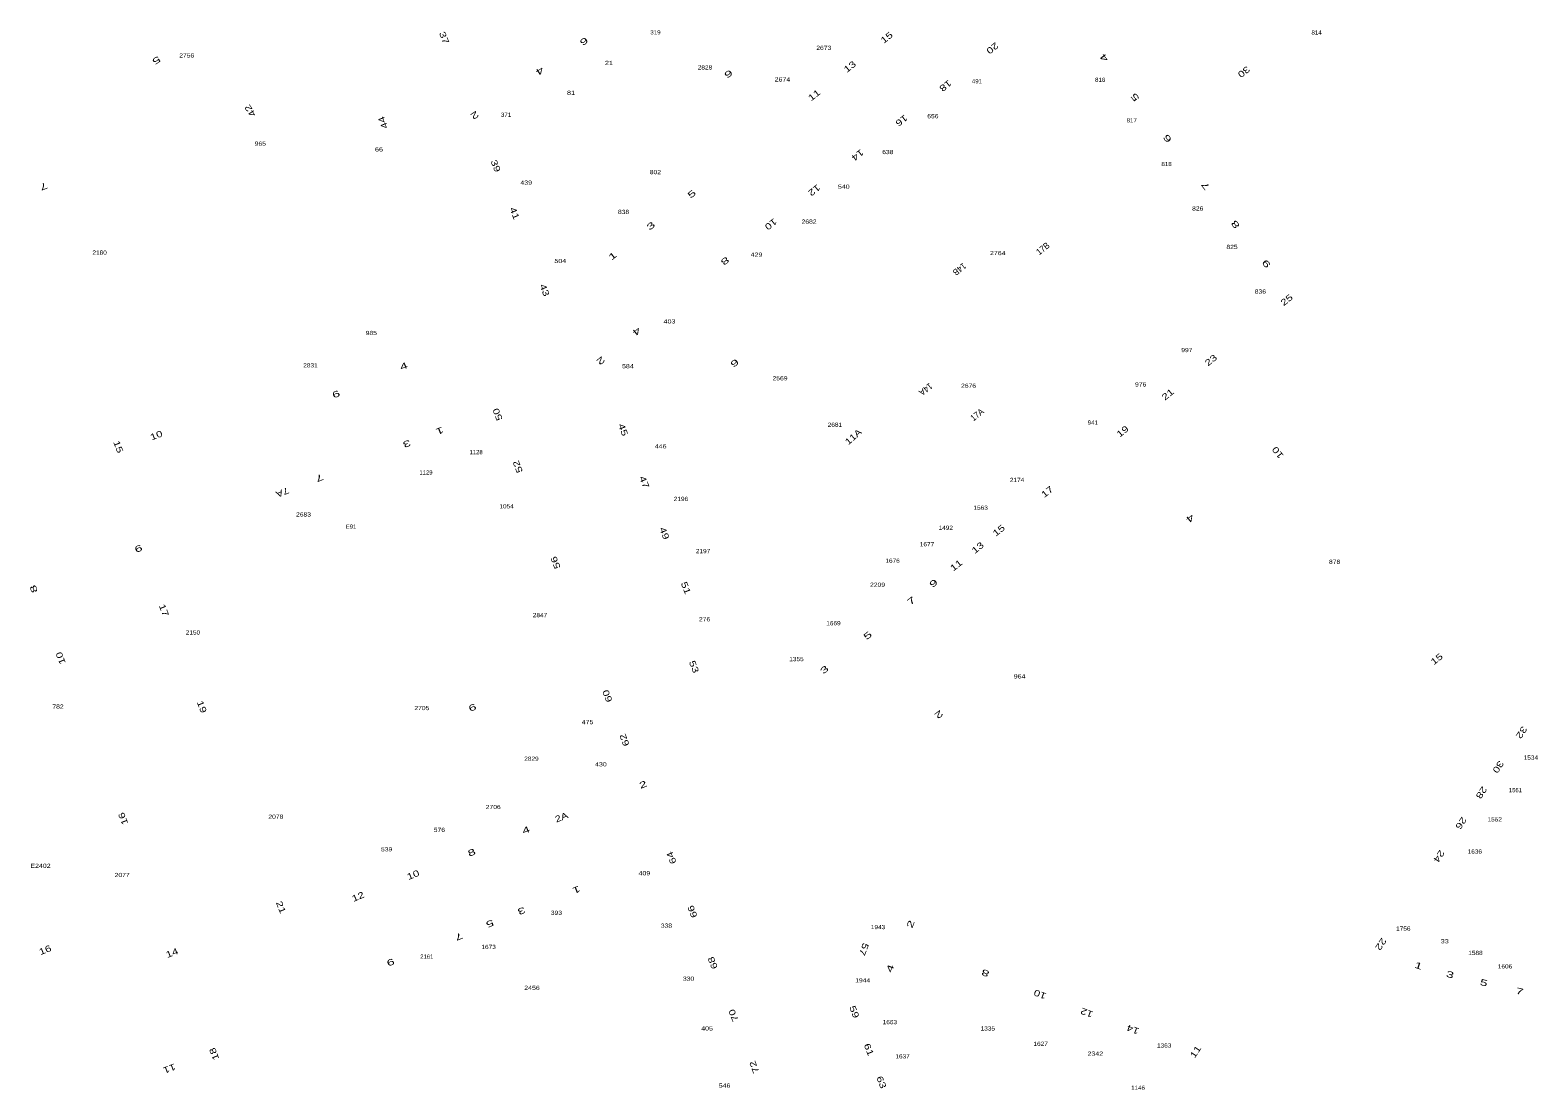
# Model space of a CAD drawing. Extents: x -828673 to -815583, y -1077737 to -1063807.
# Drawn here: x -821832.5 to -821473.2, y -1071355.2 to -1071102.6 of the extents above; entities that cross this region are included whole.
import ezdxf
from ezdxf.enums import TextEntityAlignment as Align

# ---------------------------------------------------------------- set-up
doc = ezdxf.new("R2010")
doc.units = 0
doc.header["$LTSCALE"] = 0.4
doc.layers.add('1', color=7, linetype='Continuous')
doc.layers.add('2', color=7, linetype='Continuous')

msp = doc.modelspace()

# ---------------------------------------------------------------- texts
at = {"layer": '1'}
for s, width, p in [('319', 1.1, (-821683.492, -1071103.658)), ('814', 1.1, (-821525.922, -1071103.687)), ('2756', 1.2, (-821795.197, -1071109.174)), ('2673', 1.2, (-821643.373, -1071107.358)), ('21', 1.3, (-821694.564, -1071110.951)), ('2828', 1.15, (-821671.69, -1071112.02)), ('2674', 1.25, (-821653.223, -1071114.887)), ('491', 1.1, (-821606.867, -1071115.322)), ('816', 1.1, (-821577.505, -1071114.974)), ('81', 1.3, (-821703.609, -1071118.064)), ('371', 1.1, (-821719.091, -1071123.306)), ('656', 1.2, (-821617.377, -1071123.645)), ('817', 1.1, (-821569.991, -1071124.639)), ('965', 1.2, (-821777.653, -1071130.189)), ('66', 1.3, (-821749.376, -1071131.56)), ('638', 1.2, (-821628.112, -1071132.192)), ('818', 1.1, (-821561.685, -1071135.038)), ('802', 1.2, (-821683.498, -1071136.969)), ('439', 1.25, (-821714.292, -1071139.475)), ('540', 1.25, (-821638.604, -1071140.443)), ('826', 1.2, (-821554.26, -1071145.644)), ('838', 1.2, (-821691.086, -1071146.452)), ('2682', 1.2, (-821646.878, -1071148.766)), ('2180', 1.15, (-821815.95, -1071156.15)), ('429', 1.25, (-821659.402, -1071156.641)), ('2764', 1.25, (-821601.897, -1071156.264)), ('825', 1.2, (-821546.073, -1071154.801)), ('504', 1.25, (-821706.175, -1071158.159)), ('836', 1.2, (-821539.325, -1071165.435)), ('403', 1.25, (-821680.138, -1071172.544)), ('985', 1.2, (-821751.206, -1071175.305)), ('997', 1.2, (-821556.847, -1071179.38)), ('2831', 1.15, (-821765.71, -1071183.01)), ('584', 1.25, (-821690.062, -1071183.229)), ('2569', 1.2, (-821653.795, -1071186.103)), ('2676', 1.2, (-821608.874, -1071187.873)), ('976', 1.2, (-821567.849, -1071187.569)), ('2681', 1.15, (-821640.718, -1071197.181)), ('941', 1.1, (-821579.254, -1071196.652)), ('446', 1.25, (-821682.24, -1071202.313)), ('1128', 1.05, (-821726.23, -1071203.704)), ('1129', 1.05, (-821738.179, -1071208.564)), ('2174', 1.15, (-821597.305, -1071210.322)), ('1054', 1.15, (-821718.971, -1071216.609)), ('2196', 1.15, (-821677.41, -1071214.842)), ('1563', 1.15, (-821605.982, -1071216.944)), ('2683', 1.2, (-821767.366, -1071218.549)), ('E91', 1.05, (-821756.031, -1071221.454)), ('1492', 1.15, (-821614.301, -1071221.732)), ('2197', 1.15, (-821672.139, -1071227.291)), ('1677', 1.15, (-821618.767, -1071225.659)), ('1676', 1.15, (-821626.98, -1071229.577)), ('878', 1.2, (-821521.63, -1071229.84)), ('2209', 1.2, (-821630.558, -1071235.305)), ('2847', 1.15, (-821711, -1071242.54)), ('276', 1.2, (-821671.781, -1071243.535)), ('1669', 1.15, (-821641.068, -1071244.478)), ('2150', 1.15, (-821793.703, -1071246.679)), ('1355', 1.15, (-821649.879, -1071253.025)), ('964', 1.25, (-821596.717, -1071257.148)), ('782', 1.2, (-821825.869, -1071264.342)), ('2705', 1.2, (-821739.157, -1071264.694)), ('475', 1.25, (-821699.67, -1071268.035)), ('2829', 1.15, (-821713.04, -1071276.76)), ('430', 1.25, (-821696.487, -1071278.09)), ('1534', 1.15, (-821474.866, -1071276.485)), ('1561', 1.05, (-821478.551, -1071284.259)), ('2706', 1.2, (-821722.147, -1071288.274)), ('2078', 1.2, (-821773.961, -1071290.585)), ('1552', 1.15, (-821483.474, -1071291.217)), ('576', 1.2, (-821734.986, -1071293.713)), ('539', 1.2, (-821747.55, -1071298.35)), ('1636', 1.15, (-821488.22, -1071298.886)), ('E2402', 1.25, (-821830.044, -1071302.294)), ('2077', 1.2, (-821810.58, -1071304.471)), ('409', 1.25, (-821686.111, -1071304.049)), ('393', 1.2, (-821707.091, -1071313.489)), ('338', 1.2, (-821680.873, -1071316.538)), ('1943', 1.15, (-821630.437, -1071316.887)), ('1756', 1.15, (-821505.258, -1071317.234)), ('1673', 1.15, (-821723.245, -1071321.619)), ('33', 1.3, (-821495.396, -1071320.265)), ('2161', 1.05, (-821737.98, -1071323.921)), ('1588', 1.15, (-821488.064, -1071323.041)), ('1606', 1.15, (-821481.019, -1071326.254)), ('2456', 1.25, (-821712.916, -1071331.366)), ('330', 1.2, (-821675.594, -1071329.186)), ('1944', 1.2, (-821634.09, -1071329.582)), ('1663', 1.15, (-821627.631, -1071339.54)), ('405', 1.25, (-821671.188, -1071341.038)), ('1335', 1.15, (-821604.281, -1071341.054)), ('1627', 1.15, (-821591.685, -1071344.708)), ('2342', 1.25, (-821578.668, -1071347.05)), ('1363', 1.15, (-821562.25, -1071345.113)), ('1637', 1.15, (-821624.588, -1071347.691)), ('546', 1.25, (-821667.027, -1071354.653)), ('1146', 1.1, (-821568.474, -1071355.165))]:
    msp.add_text(s, height=1, dxfattribs=dict(at, width=width)).set_placement(p, align=Align.CENTER)
at = {"layer": '2'}
for s, rotation, width, p in [('37', 291.749, 1.35, (-821734.5374, -1071104.7356)), ('6', 214.017, 1.7, (-821700.9399, -1071104.7095)), ('15', 38.644, 1.35, (-821627.9174, -1071104.9936)), ('5', 213.443, 1.7, (-821802.8222, -1071109.2218)), ('20', 219.113, 1.35, (-821603.6394, -1071106.3727)), ('4', 127.922, 1.7, (-821576.0095, -1071108.7789)), ('4', 213.703, 1.7, (-821711.4433, -1071111.7798)), ('9', 35.254, 1.7, (-821665.6609, -1071113.6951)), ('13', 38.706, 1.35, (-821636.704, -1071111.93)), ('30', 218.446, 1.35, (-821543.7147, -1071112.016)), ('18', 218.552, 1.35, (-821614.8256, -1071115.3178)), ('11', 38.356, 1.35, (-821645.2099, -1071118.714)), ('5', 128.252, 1.7, (-821568.6313, -1071118.1778)), ('42', 124.208, 1.35, (-821779.4522, -1071121.4461)), ('44', 111.397, 1.35, (-821747.7177, -1071124.4096)), ('2', 214.071, 1.7, (-821726.9643, -1071122.3082)), ('16', 218.04, 1.35, (-821625.2928, -1071123.5909)), ('6', 128.362, 1.7, (-821560.9074, -1071127.9965)), ('39', 292.089, 1.35, (-821722.246, -1071135.2585)), ('14', 218.517, 1.35, (-821635.7559, -1071131.8298)), ('7', 201.557, 1.65, (-821829.5454, -1071139.1943)), ('5', 38.3, 1.7, (-821674.3753, -1071142.2691)), ('12', 218.814, 1.35, (-821646.1129, -1071140.216)), ('7', 128.165, 1.7, (-821551.8268, -1071139.3135)), ('41', 291.446, 1.35, (-821717.7602, -1071146.5558)), ('3', 38.616, 1.7, (-821684.1321, -1071149.8594)), ('10', 218.694, 1.35, (-821656.4461, -1071148.3147)), ('8', 128.569, 1.7, (-821544.7176, -1071148.4871)), ('17B', 38.437, 0.95, (-821590.6982, -1071155.2769)), ('1', 38.767, 1.7, (-821693.2326, -1071157.0304)), ('8', 218.511, 1.7, (-821667.3785, -1071157.0728)), ('14B', 218.667, 0.95, (-821611.4954, -1071159.0454)), ('9', 128.704, 1.7, (-821537.3428, -1071157.858)), ('43', 291.494, 1.35, (-821710.6029, -1071164.8477)), ('25', 38.407, 1.35, (-821532.5954, -1071167.5226)), ('4', 218.579, 1.7, (-821688.4288, -1071173.8717)), ('2', 218.72, 1.7, (-821696.9649, -1071180.843)), ('23', 38.712, 1.35, (-821550.6531, -1071181.8688)), ('4', 21.207, 1.65, (-821743.2158, -1071183.4112)), ('6', 218.241, 1.7, (-821665.0833, -1071181.3862)), ('14A', 217.719, 0.95, (-821619.5182, -1071187.6483)), ('6', 21.379, 1.65, (-821759.3324, -1071190.0944)), ('21', 38.686, 1.35, (-821560.9218, -1071190.0335)), ('50', 111.367, 1.35, (-821720.413, -1071193.9443)), ('17A', 38.668, 0.95, (-821606.3836, -1071194.8586)), ('10', 20.998, 1.35, (-821802.1692, -1071199.8983)), ('1', 201.574, 1.65, (-821735.1457, -1071197.4257)), ('45', 290.961, 1.35, (-821691.8854, -1071198.1237)), ('11A', 41.596, 1.25, (-821635.8444, -1071200.1101)), ('19', 38.704, 1.35, (-821571.7, -1071198.8481)), ('15', 291.466, 1.35, (-821812.1897, -1071202.1955)), ('3', 201.383, 1.65, (-821743.0065, -1071200.5157)), ('10', 128.29, 1.35, (-821534.5947, -1071202.8647)), ('52', 111.563, 1.35, (-821715.6118, -1071206.4031)), ('7', 201.433, 1.65, (-821763.8169, -1071208.6563)), ('47', 292.366, 1.35, (-821686.8289, -1071210.6296)), ('7A', 201.323, 1.3, (-821772.6483, -1071212.1013)), ('17', 38.666, 1.35, (-821589.6601, -1071213.2327)), ('4', 218.182, 1.7, (-821556.5124, -1071218.411)), ('49', 291.298, 1.35, (-821682.0488, -1071222.8011)), ('15', 38.549, 1.35, (-821601.1984, -1071222.4523)), ('9', 201.498, 1.65, (-821806.9617, -1071225.5013)), ('13', 39.527, 1.35, (-821606.2133, -1071226.5605)), ('56', 111.653, 1.35, (-821706.6151, -1071229.2647)), ('11', 38.539, 1.35, (-821611.3543, -1071230.7656)), ('51', 291.208, 1.35, (-821676.921, -1071235.8422)), ('9', 38.859, 1.7, (-821616.7661, -1071235.0497)), ('8', 111.213, 1.65, (-821830.9689, -1071235.5359)), ('7', 38.68, 1.7, (-821622.0442, -1071239.2119)), ('17', 291.539, 1.35, (-821801.3226, -1071241.1517)), ('5', 37.883, 1.7, (-821632.462, -1071247.4974)), ('10', 111.221, 1.35, (-821824.5373, -1071252.029)), ('15', 38.058, 1.35, (-821496.8358, -1071253.102)), ('53', 291.378, 1.35, (-821674.9898, -1071254.6226)), ('3', 39.468, 1.7, (-821642.7562, -1071255.6295)), ('60', 111.583, 1.35, (-821694.2513, -1071261.0524)), ('19', 291.539, 1.35, (-821792.2776, -1071264.1607)), ('6', 21.075, 1.65, (-821726.8427, -1071264.7805)), ('2', 218.446, 1.7, (-821616.3937, -1071265.1573)), ('62', 110.997, 1.35, (-821690.1727, -1071271.5532)), ('32', 236.52, 1.35, (-821477.7111, -1071269.5993)), ('30', 236.327, 1.35, (-821483.2599, -1071277.8162)), ('2', 21.441, 1.65, (-821686.1882, -1071283.1226)), ('28', 236.609, 1.35, (-821487.2612, -1071283.9317)), ('16', 111.213, 1.35, (-821809.6522, -1071290.2839)), ('2A', 21.762, 1.3, (-821705.6101, -1071290.9016)), ('26', 236.545, 1.35, (-821492.1098, -1071291.214)), ('4', 21.665, 1.65, (-821714.0739, -1071293.954)), ('8', 21.145, 1.65, (-821727.0315, -1071299.3072)), ('64', 111.822, 1.35, (-821678.9775, -1071299.6078)), ('24', 236.502, 1.35, (-821497.3676, -1071299.1021)), ('10', 21.801, 1.35, (-821740.966, -1071304.6312)), ('1', 201.434, 1.65, (-821702.5739, -1071306.8013)), ('12', 23.189, 1.35, (-821754.0808, -1071309.8225)), ('21', 291.376, 1.35, (-821773.4208, -1071311.9306)), ('3', 201.494, 1.65, (-821715.6817, -1071311.8413)), ('66', 111.192, 1.35, (-821673.9797, -1071312.4376)), ('5', 201.958, 1.65, (-821723.2185, -1071314.8816)), ('2', 69.444, 1.65, (-821621.9926, -1071315.9553)), ('16', 22.042, 1.35, (-821828.662, -1071322.5432)), ('7', 201.881, 1.65, (-821730.612, -1071317.9664)), ('57', 249.001, 1.35, (-821634.5177, -1071321.4117)), ('22', 236.586, 1.35, (-821511.2288, -1071320.0425)), ('14', 21.222, 1.35, (-821798.434, -1071323.2346)), ('9', 200.749, 1.65, (-821746.8658, -1071324.0794)), ('68', 111.657, 1.35, (-821669.1452, -1071324.6458)), ('4', 69.429, 1.65, (-821626.8624, -1071326.4955)), ('8', 158.934, 1.65, (-821604.6029, -1071326.6524)), ('1', 341.085, 1.65, (-821501.8986, -1071326.2984)), ('3', 344.195, 1.65, (-821494.3238, -1071328.4188)), ('10', 159.321, 1.35, (-821591.5762, -1071331.7304)), ('5', 346.064, 1.65, (-821486.2541, -1071330.3768)), ('7', 346.913, 1.65, (-821477.7123, -1071332.4154)), ('59', 291.334, 1.35, (-821636.7958, -1071336.8711)), ('70', 112.439, 1.35, (-821664.1988, -1071337.1523)), ('12', 159.529, 1.35, (-821580.4317, -1071336.0886)), ('14', 159.114, 1.35, (-821569.4446, -1071340.0971)), ('18', 111.243, 1.35, (-821787.9617, -1071346.3587)), ('61', 291.704, 1.35, (-821633.3205, -1071345.8591)), ('11', 56.244, 1.35, (-821554.164, -1071346.5257)), ('11', 201.198, 1.35, (-821799.5713, -1071349.4138)), ('72', 110.651, 1.35, (-821659.245, -1071349.4935)), ('63', 291.682, 1.35, (-821630.3252, -1071353.6339))]:
    msp.add_text(s, height=1.5, rotation=rotation, dxfattribs=dict(at, width=width)).set_placement(p, align=Align.CENTER)

doc.saveas('drawing.dxf')
